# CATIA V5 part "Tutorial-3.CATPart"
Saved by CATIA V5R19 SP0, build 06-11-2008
Part number: Part1
Bounding box of the stored display mesh (mm): x 0 to 224, y -87.701 to 88.896, z 0 to 67.047
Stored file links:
  D:\Shriniwas\v5_r19\Part files\c09\c09_tut3.CATPart
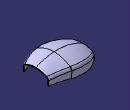
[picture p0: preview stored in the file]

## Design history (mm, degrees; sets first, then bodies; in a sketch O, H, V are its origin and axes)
Body1 (main body)
  Sketch1 on xy-plane, origin (0, 0, 0), H (1, 0, 0), V (0, 1, 0)
    arc A1 centre (95, -36.2404) radius 125 from (139.6655, 80.5072) to (0, 45) ccw
    point P1 (95, -36.2404)
    point P2 (0, 45)
    arc A2 centre (289.027, 470.911) radius 418 from (139.6655, 80.5072) to (224, 58) ccw
    point P5 (224, 58)
    radius A1 = 125
    radius A2 = 418
    distance H P2 = 45
    distance H P5 = 58
    distance P1 V = 95
    distance P2 P5 H = 224
    coincidence: P2 V
    tangency: A1 A2
  Sketch2 on xy-plane, origin (0, 0, 0), H (1, 0, 0), V (0, 1, 0)
    construction line L1 (0, -58) -> (224, -58)
    point P1 (0, -58)
    point P2 (224, -58)
    arc A1 centre (112, 154.264) radius 240 from (0, -58) to (224, -58) ccw
    length L1 = 224
    radius A1 = 240
    distance H L1 = 58
    coincidence: P1 V
    horizontal: L1 H
  Sketch3 on zx-plane, origin (0, 0, 0), H (-1, 0, 0), V (0, 0, 1)
    arc A1 centre (-126.7082, -167.9142) radius 235 from (-224, 46) to (0, 30) cw
    point P2 (0, 30)
    point P3 (-224, 46)
    radius A1 = 235
    distance H P2 = 30
    distance H P3 = 46
    distance P3 P2 H = 224
    coincidence: P2 V
  Sketch4 on yz-plane, origin (0, 0, 0), H (0, 1, 0), V (0, 0, 1)
    line L1 (-58, 0) -> (45, 0)
    point P1 (-58, 0)
    point P2 (45, 0)
    reference projected point E1 (-58, 0) from Sketch2.P1
    reference projected point E2 (45, 0) from Sketch1.P2
    construction line L2 (-58, 18.5632) -> (45, 18.5632)
    line L3 (-58, 0) -> (-58, 18.5632)
    line L4 (45, 0) -> (45, 18.5632)
    arc A1 centre (-6.5, -89.8238) radius 120 from (-58, 18.5632) to (45, 18.5632) cw
    reference projected point E3 (0, 30) from Sketch3.P2
    radius A1 = 120
    coincidence: P1 H, P1 E1, P2 E2, A1 E3
    horizontal: L2 H
    vertical: L3 V, L4 V
  Plane1: type 3Points, Element1 Sketch3.P3, Element2 Sketch2.P2, Element3 Sketch1.P5
  Sketch5 on Plane1, origin (224, 0, 0), H (0, 1, 0), V (0, 0, 1)
    line L1 (-58, 0) -> (58, 0)
    point P1 (-58, 0)
    point P2 (58, 0)
    reference projected point E1 (58, 0) from Sketch1.P5
    line L2 (-58, 0) -> (-58, 29.9794)
    line L3 (58, 0) -> (58, 29.9794)
    construction line L4 (-58, 29.9794) -> (58, 29.9794)
    reference projected point E2 (-58, 0) from Sketch2.P2
    arc A1 centre (0, -67) radius 113 from (-58, 29.9794) to (58, 29.9794) cw
    reference projected point E3 (0, 46) from Sketch3.P3
    radius A1 = 113
    coincidence: P1 H, E1 P2, E2 P1, A1 E3
    horizontal: L1 H, L4 H
    vertical: L2 V, L3 V
  Loft1: solid, Sections (Sketch4; Sketch5), Guides (Sketch1; Sketch3; Sketch2)
  Fillet1: radius 25, on edge [face of Loft1 | face of Loft1] (x2)
  Fillet2: radius 15, on edge [face of Loft1 | face of Loft1] (x3)
  Shell1: ExtOffset 0, IntOffset 3, Face (face of Loft1; face of Loft1)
